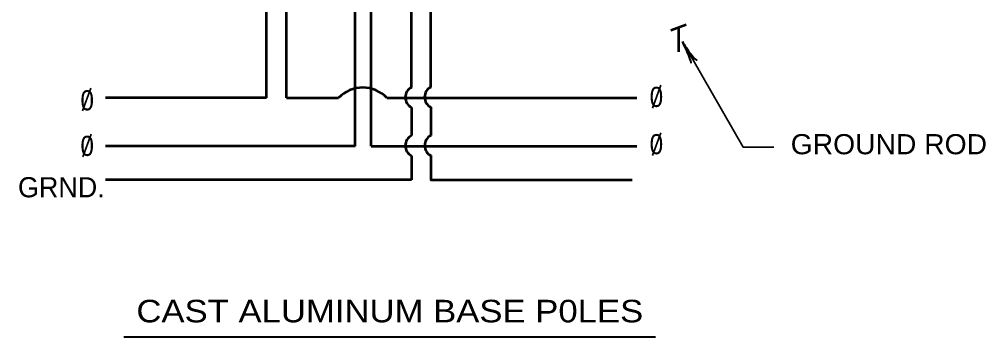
# Model space of a CAD drawing. Extents: x -217 to 639, y -295 to 249.
# Drawn here: x 89.8 to 233.7, y 24.1 to 71.4 of the extents above; entities that cross this region are included whole.
import ezdxf
from ezdxf.enums import TextEntityAlignment as Align

# ---------------------------------------------------------------- set-up
doc = ezdxf.new("R2010")
doc.units = 0
doc.header["$LTSCALE"] = 1.2
doc.layers.add('1', color=7, linetype='Continuous', lineweight=53)

msp = doc.modelspace()

# ---------------------------------------------------------------- linework, layer by layer
at = {"layer": '1'}
for p, q in [((126.586, 59.677), (126.586, 117.404)), ((129.586, 59.677), (129.586, 117.404)), ((139.786, 52.477), (139.786, 117.343)), ((142.186, 52.477), (142.186, 117.343)), ((148.186, 61.233), (148.186, 95.699)), ((151.066, 61.271), (151.066, 95.699)), ((186.837, 69.76), (189.093, 70.581)), ((187.946, 70.141), (187.946, 66.541)), ((126.586, 59.677), (102.586, 59.677)), ((129.586, 59.677), (137.325, 59.677)), ((144.525, 59.677), (181.786, 59.677)), ((148.186, 58.233), (148.186, 54.031)), ((151.066, 58.271), (151.066, 54.054)), ((139.786, 52.477), (102.586, 52.477)), ((142.186, 52.477), (181.786, 52.477)), ((148.187, 51.031), (148.187, 47.431)), ((148.187, 47.431), (102.586, 47.431))]:
    msp.add_line(p, q, dxfattribs=at)
at = {"layer": '1', "lineweight": 35}
for p, q in [((100.398, 61.114), (99.161, 57.715)), ((185.324, 61.552), (184.087, 58.152)), ((100.447, 54.26), (99.209, 50.86)), ((185.324, 54.454), (184.087, 51.055))]:
    msp.add_line(p, q, dxfattribs=at)
at = {"layer": '1', "lineweight": 40}
msp.add_line((105.347, 24.068), (184.563, 24.068), dxfattribs=at)
at = {"layer": '1', "lineweight": 35}
msp.add_lwpolyline([(202.184, 52.325), (197.626, 52.325), (188.552, 68.041)], dxfattribs=at)
at = {"layer": '1'}
msp.add_lwpolyline([(151.072, 51.054), (151.072, 47.454), (181.072, 47.454)], dxfattribs=at)
for centre, radius, start, end in [((140.925, 56.163), 5.031, 44.31179, 135.71806), ((148.95, 59.733), 1.683, 116.97883, 243.02117), ((151.83, 59.771), 1.683, 116.97883, 243.02117), ((148.951, 52.531), 1.683, 116.97883, 243.02117), ((151.836, 52.554), 1.683, 116.97883, 243.02117)]:
    msp.add_arc(centre, radius, start, end, dxfattribs=at)
at = {"layer": '1', "lineweight": 40}
for centre, major_axis, ratio, start_param, end_param in [((189.004, 66.75), (-0.871, 1.931), 0.07063, 3.1407148, 5.41811), ((189.494, 67.073), (-1.234, 1.762), 0.122415, 0.8963533, 3.1415927)]:
    msp.add_ellipse(centre, major_axis=major_axis, ratio=ratio, start_param=start_param, end_param=end_param, dxfattribs=at)

# ---------------------------------------------------------------- texts
at = {"layer": '1'}
for s, width, p in [('0', 0.9, (98.865, 57.803)), ('0', 0.9, (183.674, 58.306)), ('0', 0.9, (98.865, 51.008)), ('0', 0.9, (183.674, 51.259)), ('GROUND ROD', 1.05, (204.688, 51.259))]:
    msp.add_text(s, height=3, dxfattribs=dict(at, width=width)).set_placement(p)
msp.add_text('GRND.', height=3, dxfattribs=at).set_placement((89.553, 44.842))
at = {"layer": '1', "width": 1.15}
msp.add_text('CAST ALUMINUM BASE P0LES', height=3.36, dxfattribs=at).set_placement((144.955, 26.202), align=Align.CENTER)

doc.saveas('drawing.dxf')
